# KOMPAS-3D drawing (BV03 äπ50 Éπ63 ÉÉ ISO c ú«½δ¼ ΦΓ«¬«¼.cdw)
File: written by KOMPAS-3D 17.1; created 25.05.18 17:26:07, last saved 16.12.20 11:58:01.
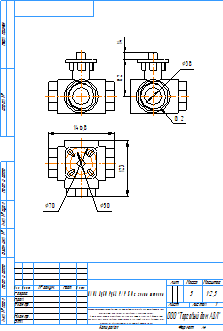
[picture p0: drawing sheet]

Sheet 1: A4, portrait

Title block, sheet 1: name: BV03 Ду50 Ру63 Р/Р ISO c голым штоком; material: Сталь 20  ГОСТ 1050-88; mass: 5; sheets: 1; sheet format: A4; stored path: C:\Users\kka\KOMPAS_Work\!Trash\BV3 кран трехходовой шаровой\KOMPAS 2D\BV03 Ду50 Ру63 РР ISO.cdw

Views: Вид 1, Проекционный вид 2, Проекционный вид 3
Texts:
  kka
  adl
  Рама для чертежей
  Лит-Масса-Масштаб
  Материал-Предприятие
  Масштаб
  Изм.
  Лист
  № докум.
  Подп.
  Дата
  Лит.
  Разраб.
  Пров.
  Т.контр.
  Листов
  Внимание! Данный продукт является объектом авторского права ООО «Торговый Дом АДЛ».
  Запрещается изменение, копирование, распространение
  (в том числе путем копирования на другие сайты и ресурсы в Интернете)
  или любое иное использование информации и объектов без предварительного
  согласия правообладателя (ООО «Торговый Дом АДЛ»).
  Н.контр.
  Утв.
  ООО "Торговый дом АДЛ"
  Изменение
  Номер документа
  Подпись
  Обозначение документа
  Наименование изделия
  Масса изделия по ГОСТ 2.109-73
  Порядковый номер листа
  Общее количество листов в документе
  Характер работы, выполненной лицом, подписавшим документ
  Наименование или индекс предприятия, выпускающего документ
  Инв. № подл.
  Подп. и дата
  Взам. инв. №
  Инв. № дубл.
  Инвентарный номер подлинника по ГОСТ 2.501-68
  Подпись принявшего подлинник в отдел технической документации
  Инвентарный номер подлинника, взамен которого выпущен данный подлинник
  Инвентарный номер дубликата по ГОСТ 2.502-68
  Подпись принявшего дубликат в отдел технической документации
  Справ. №
  Перв. примен.
  Обозначение документа, взамен или на основании которого выпущен данный документ
  Обозначение документа, в котором впервые записан данный документ
  Подпись лица, копировавшего чертеж
  Обозначение формата листа
  !Рама для чертежа
Dimensions and other numbers on the sheet: 82; 14; 38; 146,8; 123; 70; 50; 1:2,5; 1; 5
